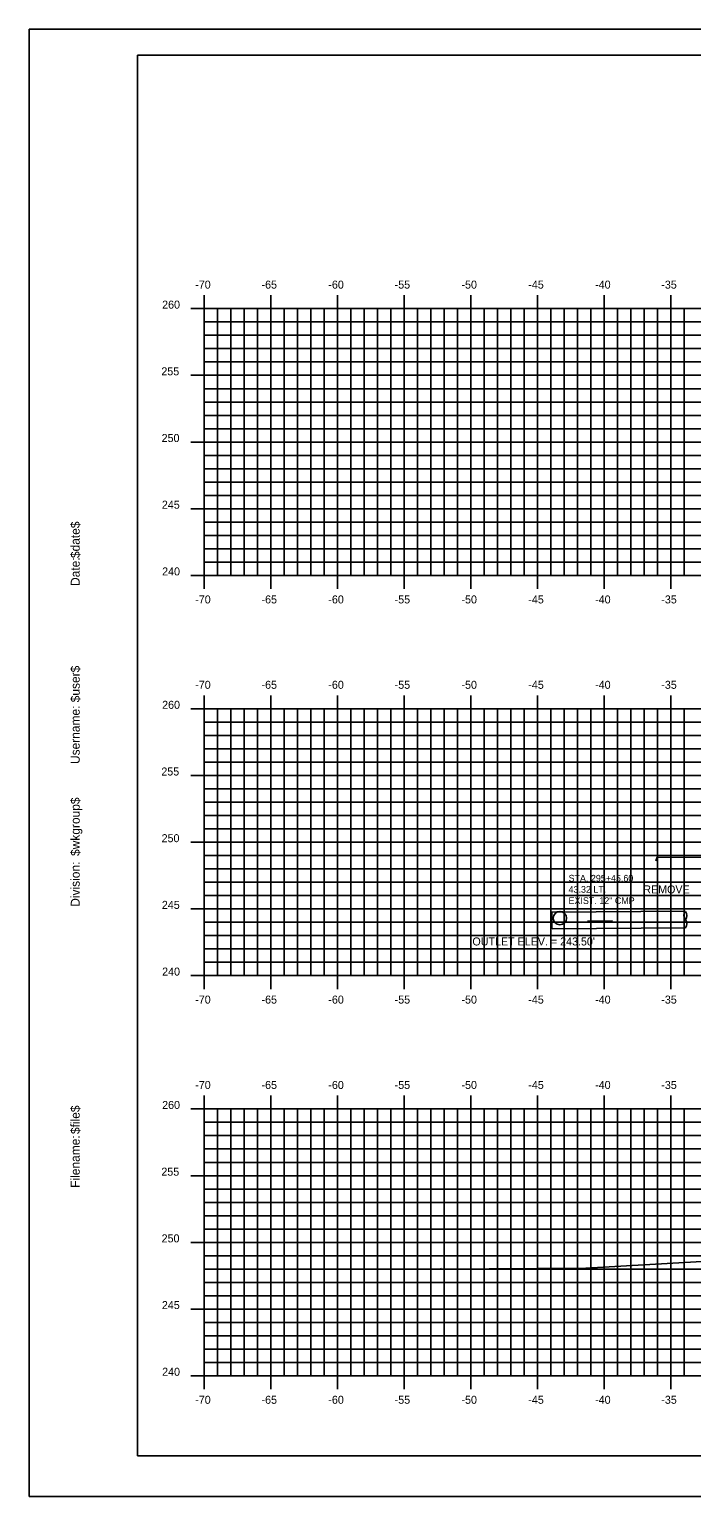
# Model space of a CAD drawing. Extents: x 859575 to 859745, y 366268 to 366378.
# Drawn here: x 859574.7 to 859624.4, y 366268.2 to 366378.2 of the extents above; entities that cross this region are included whole.
import ezdxf

# ---------------------------------------------------------------- set-up
doc = ezdxf.new("R2010")
doc.units = 0
for name, color, linetype in [('ANNOTATION', 7, 'Continuous'), ('BORDER', 7, 'Continuous'), ('D_Drainage_Culvert', 7, 'Continuous'), ('D_Text_Monospaced', 7, 'Continuous'), ('D_Text_Standard', 7, 'Continuous'), ('H_V ANNOTATION', 7, 'Continuous'), ('MAJOR', 7, 'Continuous'), ('MINOR', 7, 'Continuous'), ('PLOT BOUNDARY', 7, 'Continuous'), ('S_Drainage_Culvert_Top', 7, 'Continuous'), ('S_Roadway_Centerline', 7, 'Continuous')]:
    doc.layers.add(name, color=color, linetype=linetype)

msp = doc.modelspace()

# ---------------------------------------------------------------- linework, layer by layer
at = {"layer": 'ANNOTATION'}
msp.add_line((859618.43, 366311.34), (859616.55, 366311.33), dxfattribs=at)
at = {"layer": 'BORDER'}
for p, q in [((859742.8, 366376.24), (859582.8, 366376.24)), ((859582.8, 366376.24), (859582.8, 366271.24)), ((859582.8, 366271.24), (859742.8, 366271.24))]:
    msp.add_line(p, q, dxfattribs=at)
at = {"layer": 'D_Drainage_Culvert'}
for p, q in [((859623.88, 366312.06), (859613.88, 366311.99)), ((859613.88, 366311.99), (859613.88, 366310.74)), ((859623.89, 366310.81), (859613.9, 366310.74))]:
    msp.add_line(p, q, dxfattribs=at)
for centre, start, end in [((859624.3, 366311.75), 143.5312, 217.271), ((859623.47, 366311.74), 323.5312, 37.271), ((859623.47, 366311.12), 323.5312, 37.271)]:
    msp.add_arc(centre, 0.521, start, end, dxfattribs=at)
at = {"layer": 'MAJOR'}
for p, q in [((859586.8, 366357.24), (859587.8, 366357.24)), ((859587.8, 366358.24), (859587.8, 366357.24)), ((859587.8, 366357.24), (859727.8, 366357.24)), ((859587.8, 366337.24), (859587.8, 366357.24)), ((859587.8, 366357.24), (859727.8, 366357.24)), ((859587.8, 366337.24), (859587.8, 366357.24)), ((859587.8, 366337.24), (859587.8, 366357.24)), ((859587.8, 366357.24), (859727.8, 366357.24)), ((859592.8, 366358.24), (859592.8, 366357.24)), ((859592.8, 366337.24), (859592.8, 366357.24)), ((859592.8, 366337.24), (859592.8, 366357.24)), ((859597.8, 366358.24), (859597.8, 366357.24)), ((859597.8, 366337.24), (859597.8, 366357.24)), ((859597.8, 366337.24), (859597.8, 366357.24)), ((859602.8, 366358.24), (859602.8, 366357.24)), ((859602.8, 366337.24), (859602.8, 366357.24)), ((859602.8, 366337.24), (859602.8, 366357.24)), ((859607.8, 366358.24), (859607.8, 366357.24)), ((859607.8, 366337.24), (859607.8, 366357.24)), ((859607.8, 366337.24), (859607.8, 366357.24)), ((859612.8, 366358.24), (859612.8, 366357.24)), ((859612.8, 366337.24), (859612.8, 366357.24)), ((859612.8, 366337.24), (859612.8, 366357.24)), ((859617.8, 366358.24), (859617.8, 366357.24)), ((859617.8, 366337.24), (859617.8, 366357.24)), ((859617.8, 366337.24), (859617.8, 366357.24)), ((859622.8, 366358.24), (859622.8, 366357.24)), ((859622.8, 366337.24), (859622.8, 366357.24)), ((859622.8, 366337.24), (859622.8, 366357.24)), ((859586.8, 366352.24), (859587.8, 366352.24)), ((859587.8, 366352.24), (859727.8, 366352.24)), ((859587.8, 366352.24), (859727.8, 366352.24)), ((859586.8, 366347.24), (859587.8, 366347.24)), ((859587.8, 366347.24), (859727.8, 366347.24)), ((859587.8, 366347.24), (859727.8, 366347.24)), ((859586.8, 366342.24), (859587.8, 366342.24)), ((859587.8, 366342.24), (859727.8, 366342.24)), ((859587.8, 366342.24), (859727.8, 366342.24)), ((859586.8, 366337.24), (859587.8, 366337.24)), ((859587.8, 366337.24), (859727.8, 366337.24)), ((859587.8, 366337.24), (859727.8, 366337.24)), ((859587.8, 366337.24), (859727.8, 366337.24)), ((859587.8, 366336.23), (859587.8, 366337.24)), ((859592.8, 366336.23), (859592.8, 366337.24)), ((859597.8, 366336.23), (859597.8, 366337.24)), ((859602.8, 366336.23), (859602.8, 366337.24)), ((859607.8, 366336.23), (859607.8, 366337.24)), ((859612.8, 366336.23), (859612.8, 366337.24)), ((859617.8, 366336.23), (859617.8, 366337.24)), ((859622.8, 366336.23), (859622.8, 366337.24)), ((859587.8, 366328.24), (859587.8, 366327.24)), ((859592.8, 366328.24), (859592.8, 366327.24)), ((859597.8, 366328.24), (859597.8, 366327.24)), ((859602.8, 366328.24), (859602.8, 366327.24)), ((859607.8, 366328.24), (859607.8, 366327.24)), ((859612.8, 366328.24), (859612.8, 366327.24)), ((859617.8, 366328.24), (859617.8, 366327.24)), ((859622.8, 366328.24), (859622.8, 366327.24)), ((859586.8, 366327.24), (859587.8, 366327.24)), ((859587.8, 366327.24), (859727.8, 366327.24)), ((859587.8, 366307.24), (859587.8, 366327.24)), ((859587.8, 366307.24), (859587.8, 366327.24)), ((859587.8, 366327.24), (859727.8, 366327.24)), ((859592.8, 366307.24), (859592.8, 366327.24)), ((859597.8, 366307.24), (859597.8, 366327.24)), ((859602.8, 366307.24), (859602.8, 366327.24)), ((859607.8, 366307.24), (859607.8, 366327.24)), ((859612.8, 366307.24), (859612.8, 366327.24)), ((859617.8, 366307.24), (859617.8, 366327.24)), ((859622.8, 366307.24), (859622.8, 366327.24)), ((859586.8, 366322.24), (859587.8, 366322.24)), ((859587.8, 366322.24), (859727.8, 366322.24)), ((859586.8, 366317.24), (859587.8, 366317.24)), ((859587.8, 366317.24), (859727.8, 366317.24)), ((859586.8, 366312.24), (859587.8, 366312.24)), ((859587.8, 366312.24), (859727.8, 366312.24)), ((859586.8, 366307.24), (859587.8, 366307.24)), ((859587.8, 366307.24), (859727.8, 366307.24)), ((859587.8, 366307.24), (859727.8, 366307.24)), ((859587.8, 366306.23), (859587.8, 366307.24)), ((859592.8, 366306.23), (859592.8, 366307.24)), ((859597.8, 366306.23), (859597.8, 366307.24)), ((859602.8, 366306.23), (859602.8, 366307.24)), ((859607.8, 366306.23), (859607.8, 366307.24)), ((859612.8, 366306.23), (859612.8, 366307.24)), ((859617.8, 366306.23), (859617.8, 366307.24)), ((859622.8, 366306.23), (859622.8, 366307.24)), ((859587.8, 366298.24), (859587.8, 366297.24)), ((859592.8, 366298.24), (859592.8, 366297.24)), ((859597.8, 366298.24), (859597.8, 366297.24)), ((859602.8, 366298.24), (859602.8, 366297.24)), ((859607.8, 366298.24), (859607.8, 366297.24)), ((859612.8, 366298.24), (859612.8, 366297.24)), ((859617.8, 366298.24), (859617.8, 366297.24)), ((859622.8, 366298.24), (859622.8, 366297.24)), ((859586.8, 366297.24), (859587.8, 366297.24)), ((859587.8, 366297.24), (859727.8, 366297.24)), ((859587.8, 366277.24), (859587.8, 366297.24)), ((859587.8, 366277.24), (859587.8, 366297.24)), ((859587.8, 366297.24), (859727.8, 366297.24)), ((859592.8, 366277.24), (859592.8, 366297.24)), ((859597.8, 366277.24), (859597.8, 366297.24)), ((859602.8, 366277.24), (859602.8, 366297.24)), ((859607.8, 366277.24), (859607.8, 366297.24)), ((859612.8, 366277.24), (859612.8, 366297.24)), ((859617.8, 366277.24), (859617.8, 366297.24)), ((859622.8, 366277.24), (859622.8, 366297.24)), ((859586.8, 366292.24), (859587.8, 366292.24)), ((859587.8, 366292.24), (859727.8, 366292.24)), ((859586.8, 366287.24), (859587.8, 366287.24)), ((859587.8, 366287.24), (859727.8, 366287.24)), ((859586.8, 366282.24), (859587.8, 366282.24)), ((859587.8, 366282.24), (859727.8, 366282.24)), ((859586.8, 366277.24), (859587.8, 366277.24)), ((859587.8, 366277.24), (859727.8, 366277.24)), ((859587.8, 366277.24), (859727.8, 366277.24)), ((859587.8, 366276.23), (859587.8, 366277.24)), ((859592.8, 366276.23), (859592.8, 366277.24)), ((859597.8, 366276.23), (859597.8, 366277.24)), ((859602.8, 366276.23), (859602.8, 366277.24)), ((859607.8, 366276.23), (859607.8, 366277.24)), ((859612.8, 366276.23), (859612.8, 366277.24)), ((859617.8, 366276.23), (859617.8, 366277.24)), ((859622.8, 366276.23), (859622.8, 366277.24))]:
    msp.add_line(p, q, dxfattribs=at)
at = {"layer": 'MINOR'}
for p, q in [((859588.8, 366337.24), (859588.8, 366357.24)), ((859588.8, 366337.24), (859588.8, 366357.24)), ((859589.8, 366337.24), (859589.8, 366357.24)), ((859589.8, 366337.24), (859589.8, 366357.24)), ((859590.8, 366337.24), (859590.8, 366357.24)), ((859590.8, 366337.24), (859590.8, 366357.24)), ((859591.8, 366337.24), (859591.8, 366357.24)), ((859591.8, 366337.24), (859591.8, 366357.24)), ((859593.8, 366337.24), (859593.8, 366357.24)), ((859593.8, 366337.24), (859593.8, 366357.24)), ((859594.8, 366337.24), (859594.8, 366357.24)), ((859594.8, 366337.24), (859594.8, 366357.24)), ((859595.8, 366337.24), (859595.8, 366357.24)), ((859595.8, 366337.24), (859595.8, 366357.24)), ((859596.8, 366337.24), (859596.8, 366357.24)), ((859596.8, 366337.24), (859596.8, 366357.24)), ((859598.8, 366337.24), (859598.8, 366357.24)), ((859598.8, 366337.24), (859598.8, 366357.24)), ((859599.8, 366337.24), (859599.8, 366357.24)), ((859599.8, 366337.24), (859599.8, 366357.24)), ((859600.8, 366337.24), (859600.8, 366357.24)), ((859600.8, 366337.24), (859600.8, 366357.24)), ((859601.8, 366337.24), (859601.8, 366357.24)), ((859601.8, 366337.24), (859601.8, 366357.24)), ((859603.8, 366337.24), (859603.8, 366357.24)), ((859603.8, 366337.24), (859603.8, 366357.24)), ((859604.8, 366337.24), (859604.8, 366357.24)), ((859604.8, 366337.24), (859604.8, 366357.24)), ((859605.8, 366337.24), (859605.8, 366357.24)), ((859605.8, 366337.24), (859605.8, 366357.24)), ((859606.8, 366337.24), (859606.8, 366357.24)), ((859606.8, 366337.24), (859606.8, 366357.24)), ((859608.8, 366337.24), (859608.8, 366357.24)), ((859608.8, 366337.24), (859608.8, 366357.24)), ((859609.8, 366337.24), (859609.8, 366357.24)), ((859609.8, 366337.24), (859609.8, 366357.24)), ((859610.8, 366337.24), (859610.8, 366357.24)), ((859610.8, 366337.24), (859610.8, 366357.24)), ((859611.8, 366337.24), (859611.8, 366357.24)), ((859611.8, 366337.24), (859611.8, 366357.24)), ((859613.8, 366337.24), (859613.8, 366357.24)), ((859613.8, 366337.24), (859613.8, 366357.24)), ((859614.8, 366337.24), (859614.8, 366357.24)), ((859614.8, 366337.24), (859614.8, 366357.24)), ((859615.8, 366337.24), (859615.8, 366357.24)), ((859615.8, 366337.24), (859615.8, 366357.24)), ((859616.8, 366337.24), (859616.8, 366357.24)), ((859616.8, 366337.24), (859616.8, 366357.24)), ((859618.8, 366337.24), (859618.8, 366357.24)), ((859618.8, 366337.24), (859618.8, 366357.24)), ((859619.8, 366337.24), (859619.8, 366357.24)), ((859619.8, 366337.24), (859619.8, 366357.24)), ((859620.8, 366337.24), (859620.8, 366357.24)), ((859620.8, 366337.24), (859620.8, 366357.24)), ((859621.8, 366337.24), (859621.8, 366357.24)), ((859621.8, 366337.24), (859621.8, 366357.24)), ((859623.8, 366337.24), (859623.8, 366357.24)), ((859623.8, 366337.24), (859623.8, 366357.24)), ((859587.8, 366356.24), (859727.8, 366356.24)), ((859587.8, 366356.24), (859727.8, 366356.24)), ((859587.8, 366356.24), (859588.8, 366356.24)), ((859587.8, 366355.24), (859727.8, 366355.24)), ((859587.8, 366355.24), (859727.8, 366355.24)), ((859587.8, 366355.24), (859588.8, 366355.24)), ((859587.8, 366354.24), (859727.8, 366354.24)), ((859587.8, 366354.24), (859727.8, 366354.24)), ((859587.8, 366354.24), (859588.8, 366354.24)), ((859587.8, 366353.24), (859727.8, 366353.24)), ((859587.8, 366353.24), (859727.8, 366353.24)), ((859587.8, 366353.24), (859588.8, 366353.24)), ((859587.8, 366351.24), (859727.8, 366351.24)), ((859587.8, 366351.24), (859727.8, 366351.24)), ((859587.8, 366351.24), (859588.8, 366351.24)), ((859587.8, 366350.24), (859727.8, 366350.24)), ((859587.8, 366350.24), (859727.8, 366350.24)), ((859587.8, 366350.24), (859588.8, 366350.24)), ((859587.8, 366349.24), (859727.8, 366349.24)), ((859587.8, 366349.24), (859727.8, 366349.24)), ((859587.8, 366349.24), (859588.8, 366349.24)), ((859587.8, 366348.24), (859727.8, 366348.24)), ((859587.8, 366348.24), (859727.8, 366348.24)), ((859587.8, 366348.24), (859588.8, 366348.24)), ((859587.8, 366346.24), (859727.8, 366346.24)), ((859587.8, 366346.24), (859727.8, 366346.24)), ((859587.8, 366346.24), (859588.8, 366346.24)), ((859587.8, 366345.24), (859727.8, 366345.24)), ((859587.8, 366345.24), (859727.8, 366345.24)), ((859587.8, 366345.24), (859588.8, 366345.24)), ((859587.8, 366344.24), (859727.8, 366344.24)), ((859587.8, 366344.24), (859727.8, 366344.24)), ((859587.8, 366344.24), (859588.8, 366344.24)), ((859587.8, 366343.24), (859727.8, 366343.24)), ((859587.8, 366343.24), (859727.8, 366343.24)), ((859587.8, 366343.24), (859588.8, 366343.24)), ((859587.8, 366341.24), (859727.8, 366341.24)), ((859587.8, 366341.24), (859727.8, 366341.24)), ((859587.8, 366341.24), (859588.8, 366341.24)), ((859587.8, 366340.24), (859727.8, 366340.24)), ((859587.8, 366340.24), (859727.8, 366340.24)), ((859587.8, 366340.24), (859588.8, 366340.24)), ((859587.8, 366339.24), (859727.8, 366339.24)), ((859587.8, 366339.24), (859727.8, 366339.24)), ((859587.8, 366339.24), (859588.8, 366339.24)), ((859587.8, 366338.24), (859727.8, 366338.24)), ((859587.8, 366338.24), (859727.8, 366338.24)), ((859587.8, 366338.24), (859588.8, 366338.24)), ((859588.8, 366307.24), (859588.8, 366327.24)), ((859589.8, 366307.24), (859589.8, 366327.24)), ((859590.8, 366307.24), (859590.8, 366327.24)), ((859591.8, 366307.24), (859591.8, 366327.24)), ((859593.8, 366307.24), (859593.8, 366327.24)), ((859594.8, 366307.24), (859594.8, 366327.24)), ((859595.8, 366307.24), (859595.8, 366327.24)), ((859596.8, 366307.24), (859596.8, 366327.24)), ((859598.8, 366307.24), (859598.8, 366327.24)), ((859599.8, 366307.24), (859599.8, 366327.24)), ((859600.8, 366307.24), (859600.8, 366327.24)), ((859601.8, 366307.24), (859601.8, 366327.24)), ((859603.8, 366307.24), (859603.8, 366327.24)), ((859604.8, 366307.24), (859604.8, 366327.24)), ((859605.8, 366307.24), (859605.8, 366327.24)), ((859606.8, 366307.24), (859606.8, 366327.24)), ((859608.8, 366307.24), (859608.8, 366327.24)), ((859609.8, 366307.24), (859609.8, 366327.24)), ((859610.8, 366307.24), (859610.8, 366327.24)), ((859611.8, 366307.24), (859611.8, 366327.24)), ((859613.8, 366307.24), (859613.8, 366327.24)), ((859614.8, 366307.24), (859614.8, 366327.24)), ((859615.8, 366307.24), (859615.8, 366327.24)), ((859616.8, 366307.24), (859616.8, 366327.24)), ((859618.8, 366307.24), (859618.8, 366327.24)), ((859619.8, 366307.24), (859619.8, 366327.24)), ((859620.8, 366307.24), (859620.8, 366327.24)), ((859621.8, 366307.24), (859621.8, 366327.24)), ((859623.8, 366307.24), (859623.8, 366327.24)), ((859587.8, 366326.24), (859727.8, 366326.24)), ((859587.8, 366326.24), (859588.8, 366326.24)), ((859587.8, 366325.24), (859727.8, 366325.24)), ((859587.8, 366325.24), (859588.8, 366325.24)), ((859587.8, 366324.24), (859727.8, 366324.24)), ((859587.8, 366324.24), (859588.8, 366324.24)), ((859587.8, 366323.24), (859727.8, 366323.24)), ((859587.8, 366323.24), (859588.8, 366323.24)), ((859587.8, 366321.24), (859727.8, 366321.24)), ((859587.8, 366321.24), (859588.8, 366321.24)), ((859587.8, 366320.24), (859727.8, 366320.24)), ((859587.8, 366320.24), (859588.8, 366320.24)), ((859587.8, 366319.24), (859727.8, 366319.24)), ((859587.8, 366319.24), (859588.8, 366319.24)), ((859587.8, 366318.24), (859727.8, 366318.24)), ((859587.8, 366318.24), (859588.8, 366318.24)), ((859587.8, 366316.24), (859727.8, 366316.24)), ((859587.8, 366316.24), (859588.8, 366316.24)), ((859587.8, 366315.24), (859727.8, 366315.24)), ((859587.8, 366315.24), (859588.8, 366315.24)), ((859587.8, 366314.24), (859727.8, 366314.24)), ((859587.8, 366314.24), (859588.8, 366314.24)), ((859587.8, 366313.24), (859727.8, 366313.24)), ((859587.8, 366313.24), (859588.8, 366313.24)), ((859587.8, 366311.24), (859727.8, 366311.24)), ((859587.8, 366311.24), (859588.8, 366311.24)), ((859587.8, 366310.24), (859727.8, 366310.24)), ((859587.8, 366310.24), (859588.8, 366310.24)), ((859587.8, 366309.24), (859727.8, 366309.24)), ((859587.8, 366309.24), (859588.8, 366309.24)), ((859587.8, 366308.24), (859727.8, 366308.24)), ((859587.8, 366308.24), (859588.8, 366308.24)), ((859587.8, 366277.24), (859587.8, 366297.24)), ((859588.8, 366277.24), (859588.8, 366297.24)), ((859589.8, 366277.24), (859589.8, 366297.24)), ((859590.8, 366277.24), (859590.8, 366297.24)), ((859591.8, 366277.24), (859591.8, 366297.24)), ((859593.8, 366277.24), (859593.8, 366297.24)), ((859594.8, 366277.24), (859594.8, 366297.24)), ((859595.8, 366277.24), (859595.8, 366297.24)), ((859596.8, 366277.24), (859596.8, 366297.24)), ((859598.8, 366277.24), (859598.8, 366297.24)), ((859599.8, 366277.24), (859599.8, 366297.24)), ((859600.8, 366277.24), (859600.8, 366297.24)), ((859601.8, 366277.24), (859601.8, 366297.24)), ((859603.8, 366277.24), (859603.8, 366297.24)), ((859604.8, 366277.24), (859604.8, 366297.24)), ((859605.8, 366277.24), (859605.8, 366297.24)), ((859606.8, 366277.24), (859606.8, 366297.24)), ((859608.8, 366277.24), (859608.8, 366297.24)), ((859609.8, 366277.24), (859609.8, 366297.24)), ((859610.8, 366277.24), (859610.8, 366297.24)), ((859611.8, 366277.24), (859611.8, 366297.24)), ((859613.8, 366277.24), (859613.8, 366297.24)), ((859614.8, 366277.24), (859614.8, 366297.24)), ((859615.8, 366277.24), (859615.8, 366297.24)), ((859616.8, 366277.24), (859616.8, 366297.24)), ((859618.8, 366277.24), (859618.8, 366297.24)), ((859619.8, 366277.24), (859619.8, 366297.24)), ((859620.8, 366277.24), (859620.8, 366297.24)), ((859621.8, 366277.24), (859621.8, 366297.24)), ((859623.8, 366277.24), (859623.8, 366297.24)), ((859587.8, 366296.24), (859727.8, 366296.24)), ((859587.8, 366296.24), (859588.8, 366296.24)), ((859587.8, 366295.24), (859727.8, 366295.24)), ((859587.8, 366295.24), (859588.8, 366295.24)), ((859587.8, 366294.24), (859727.8, 366294.24)), ((859587.8, 366294.24), (859588.8, 366294.24)), ((859587.8, 366293.24), (859727.8, 366293.24)), ((859587.8, 366293.24), (859588.8, 366293.24)), ((859587.8, 366291.24), (859727.8, 366291.24)), ((859587.8, 366291.24), (859588.8, 366291.24)), ((859587.8, 366290.24), (859727.8, 366290.24)), ((859587.8, 366290.24), (859588.8, 366290.24)), ((859587.8, 366289.24), (859727.8, 366289.24)), ((859587.8, 366289.24), (859588.8, 366289.24)), ((859587.8, 366288.24), (859727.8, 366288.24)), ((859587.8, 366288.24), (859588.8, 366288.24)), ((859587.8, 366286.24), (859727.8, 366286.24)), ((859587.8, 366286.24), (859588.8, 366286.24)), ((859587.8, 366285.24), (859727.8, 366285.24)), ((859587.8, 366285.24), (859588.8, 366285.24)), ((859587.8, 366284.24), (859727.8, 366284.24)), ((859587.8, 366284.24), (859588.8, 366284.24)), ((859587.8, 366283.24), (859727.8, 366283.24)), ((859587.8, 366283.24), (859588.8, 366283.24)), ((859587.8, 366281.24), (859727.8, 366281.24)), ((859587.8, 366281.24), (859588.8, 366281.24)), ((859587.8, 366280.24), (859727.8, 366280.24)), ((859587.8, 366280.24), (859588.8, 366280.24)), ((859587.8, 366279.24), (859727.8, 366279.24)), ((859587.8, 366279.24), (859588.8, 366279.24)), ((859587.8, 366278.24), (859727.8, 366278.24)), ((859587.8, 366278.24), (859588.8, 366278.24))]:
    msp.add_line(p, q, dxfattribs=at)
at = {"layer": 'PLOT BOUNDARY'}
msp.add_lwpolyline([(859574.7, 366268.18), (859744.7, 366268.18), (859744.7, 366378.18), (859574.7, 366378.18)], close=True, dxfattribs=at)
at = {"layer": 'S_Drainage_Culvert_Top'}
msp.add_circle((859614.48, 366311.55), 0.5, dxfattribs=at)
at = {"layer": 'S_Roadway_Centerline'}
for points in [[(859621.67, 366315.85), (859621.76, 366316.11), (859625.99, 366316.1)], [(859605.52, 366285.31), (859605.56, 366285.24), (859616.42, 366285.3), (859625.56, 366285.83)]]:
    msp.add_lwpolyline(points, dxfattribs=at)

# ---------------------------------------------------------------- texts
at = {"layer": 'BORDER'}
for s, p in [('$date$', (859578.48, 366338.54)), ('Date:', (859578.48, 366336.45)), ('$user$', (859578.48, 366327.73)), ('Username:', (859578.48, 366323.1)), ('$wkgroup$', (859578.48, 366316.21)), ('Division:', (859578.48, 366312.4)), ('$file$', (859578.48, 366295.36)), ('Filename:', (859578.48, 366291.33))]:
    msp.add_text(s, height=0.67, rotation=90, dxfattribs=at).set_placement(p)
at = {"layer": 'D_Text_Monospaced'}
for s, p in [('STA. 295+45.60', (859615.13, 366314.29)), ('43.32 LT.', (859615.13, 366313.45)), ('EXIST. 12" CMP', (859615.13, 366312.61))]:
    msp.add_text(s, height=0.5, dxfattribs=at).set_placement(p)
at = {"layer": 'D_Text_Standard'}
for s, p in [('REMOVE', (859620.73, 366313.4)), ("OUTLET ELEV. = 243.50'", (859607.92, 366309.5))]:
    msp.add_text(s, height=0.6, dxfattribs=at).set_placement(p)
at = {"layer": 'H_V ANNOTATION'}
for s, p in [('-70', (859587.14, 366358.74)), ('-65', (859592.11, 366358.74)), ('-60', (859597.12, 366358.74)), ('-55', (859602.09, 366358.74)), ('-50', (859607.1, 366358.74)), ('-45', (859612.11, 366358.74)), ('-40', (859617.12, 366358.74)), ('-35', (859622.08, 366358.74)), ('260', (859584.66, 366357.24)), ('255', (859584.6, 366352.24)), ('250', (859584.62, 366347.24)), ('245', (859584.64, 366342.24)), ('240', (859584.66, 366337.24)), ('-70', (859587.14, 366335.14)), ('-65', (859592.11, 366335.14)), ('-60', (859597.12, 366335.14)), ('-55', (859602.09, 366335.14)), ('-50', (859607.1, 366335.14)), ('-45', (859612.11, 366335.14)), ('-40', (859617.12, 366335.14)), ('-35', (859622.08, 366335.14)), ('-70', (859587.14, 366328.74)), ('-65', (859592.11, 366328.74)), ('-60', (859597.12, 366328.74)), ('-55', (859602.09, 366328.74)), ('-50', (859607.1, 366328.74)), ('-45', (859612.11, 366328.74)), ('-40', (859617.12, 366328.74)), ('-35', (859622.08, 366328.74)), ('260', (859584.66, 366327.24)), ('255', (859584.6, 366322.24)), ('250', (859584.62, 366317.24)), ('245', (859584.64, 366312.24)), ('240', (859584.66, 366307.24)), ('-70', (859587.14, 366305.14)), ('-65', (859592.11, 366305.14)), ('-60', (859597.12, 366305.14)), ('-55', (859602.09, 366305.14)), ('-50', (859607.1, 366305.14)), ('-45', (859612.11, 366305.14)), ('-40', (859617.12, 366305.14)), ('-35', (859622.08, 366305.14)), ('-70', (859587.14, 366298.74)), ('-65', (859592.11, 366298.74)), ('-60', (859597.12, 366298.74)), ('-55', (859602.09, 366298.74)), ('-50', (859607.1, 366298.74)), ('-45', (859612.11, 366298.74)), ('-40', (859617.12, 366298.74)), ('-35', (859622.08, 366298.74)), ('260', (859584.66, 366297.24)), ('255', (859584.6, 366292.24)), ('250', (859584.62, 366287.24)), ('245', (859584.64, 366282.24)), ('240', (859584.66, 366277.24)), ('-70', (859587.14, 366275.14)), ('-65', (859592.11, 366275.14)), ('-60', (859597.12, 366275.14)), ('-55', (859602.09, 366275.14)), ('-50', (859607.1, 366275.14)), ('-45', (859612.11, 366275.14)), ('-40', (859617.12, 366275.14)), ('-35', (859622.08, 366275.14))]:
    msp.add_text(s, height=0.6, dxfattribs=at).set_placement(p)

doc.saveas('drawing.dxf')
